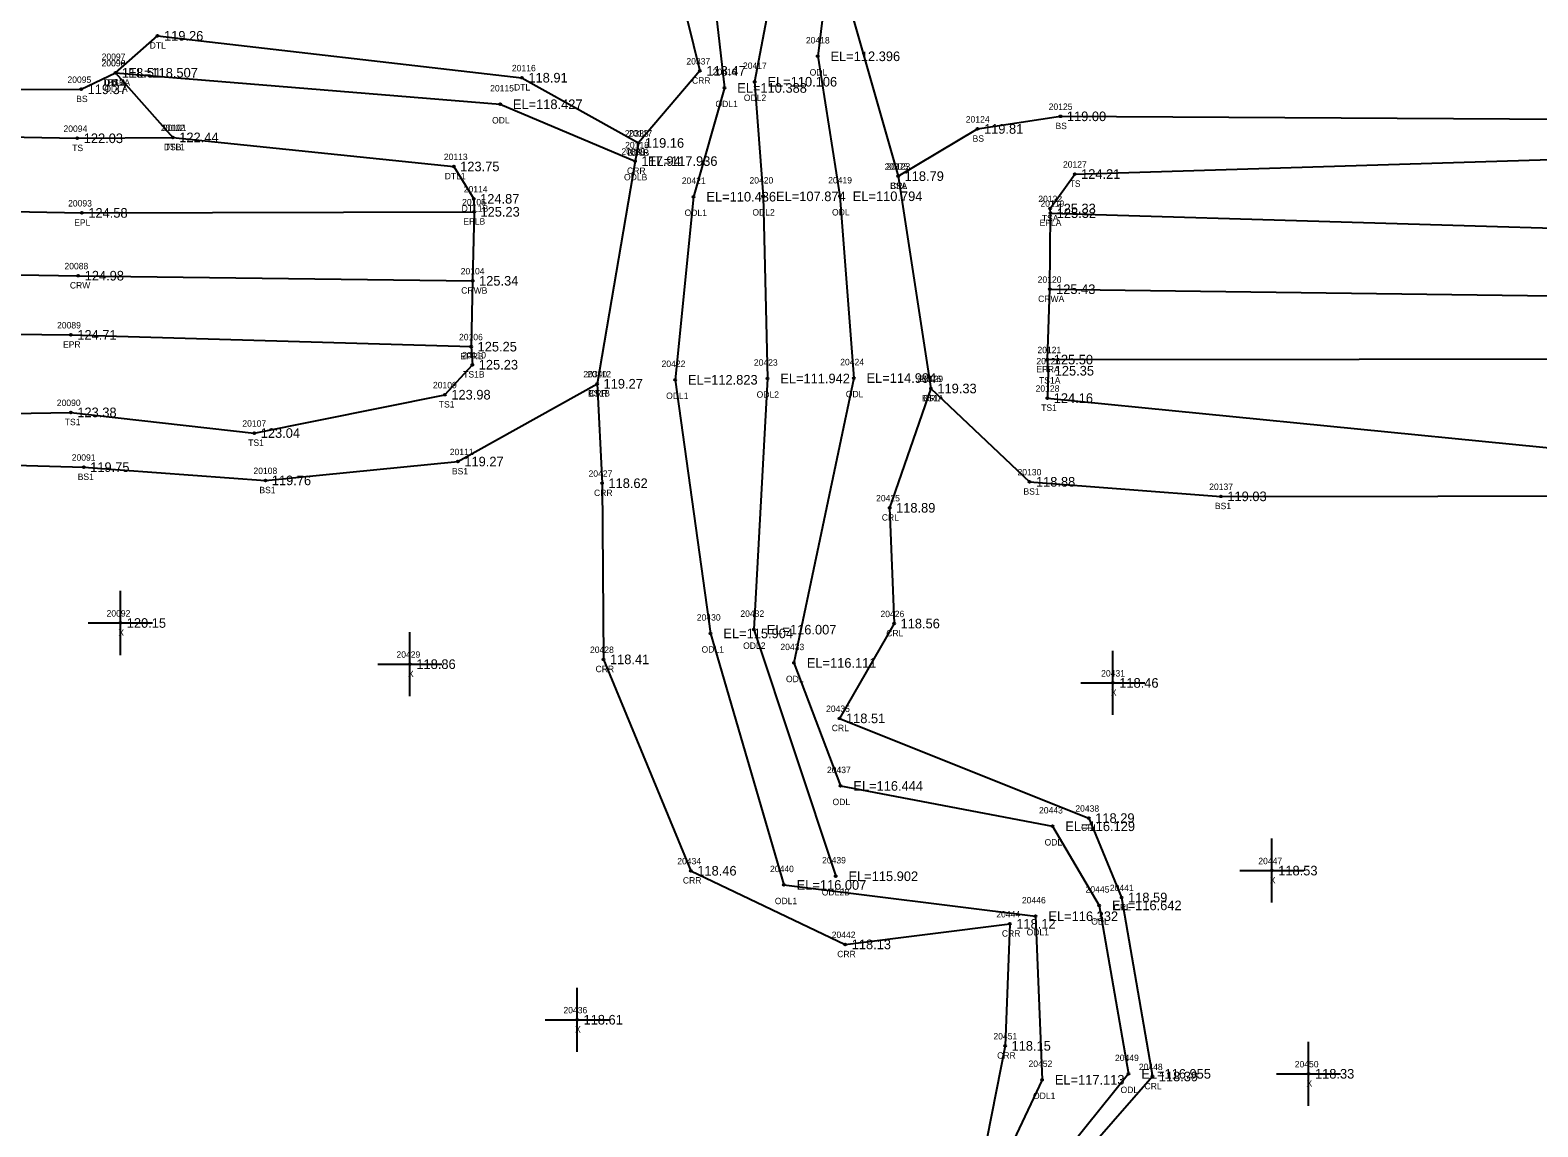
# Model space of a CAD drawing. Extents: x 2375812 to 2377225, y 1024470 to 1025135.
# Drawn here: x 2376402.6 to 2376638, y 1024795.6 to 1024966.8 of the extents above; entities that cross this region are included whole.
import ezdxf

# ---------------------------------------------------------------- set-up
doc = ezdxf.new("R2010")
doc.units = 0
for name, color, linetype in [('RD_DTM_BkLn1', 7, 'Continuous'), ('RD_DTM_BkLn2', 7, 'Continuous'), ('RD_DTM_BkLn_txCode', 7, 'Continuous'), ('RD_EX_H2O', 7, 'Continuous'), ('RD_EX_H2O_txCode', 7, 'Continuous'), ('RD_EX_Misc', 7, 'Continuous'), ('RD_EX_Misc_txCode', 7, 'Continuous'), ('RD_EX_Road', 7, 'Continuous'), ('RD_EX_Road_txCode', 7, 'Continuous'), ('RD_EX_TX_H2O_ELEV', 7, 'Continuous'), ('RD_EX_TX_Misc_ELEV', 7, 'Continuous'), ('RD_EX_TX_Road_ELEV', 7, 'Continuous'), ('RD_HC_Survey_ELEV', 7, 'Continuous'), ('RD_HC_Survey_txCode', 7, 'Continuous'), ('RD_SMD_Locator', 7, 'Continuous')]:
    doc.layers.add(name, color=color, linetype=linetype)

msp = doc.modelspace()

# ---------------------------------------------------------------- linework, layer by layer
at = {"layer": 'RD_DTM_BkLn1'}
for points in [[(2375816.52, 1024916.17), (2375868.08, 1024924.19), (2375918.61, 1024929.17), (2375973.79, 1024932.27), (2376030.31, 1024933.43), (2376124.39, 1024932.38), (2376221.5, 1024931.17), (2376315.07, 1024930.06), (2376410.07, 1024928.46), (2376471.65, 1024927.66)], [(2376561.75, 1024926.35), (2376659.86, 1024925.07), (2376762.41, 1024923.95), (2376865.76, 1024922.65), (2376965.3, 1024921.9), (2377063.64, 1024920.86), (2377113.34, 1024920.1), (2377166.94, 1024920.12), (2377217.3, 1024921.22)]]:
    msp.add_lwpolyline(points, dxfattribs=at)
at = {"layer": 'RD_DTM_BkLn2'}
for points in [[(2376029.54, 1024960.61), (2376031.93, 1024960.3), (2376124.75, 1024960.87), (2376220.58, 1024959.2), (2376313.51, 1024957.48), (2376410.53, 1024957.56), (2376415.87, 1024960.14)], [(2376030.33, 1024957.29), (2376124.82, 1024955.55), (2376220.6, 1024953.97), (2376313.35, 1024951.76), (2376409.92, 1024949.91), (2376424.84, 1024950.05)], [(2376538.09, 1024944), (2376550.49, 1024951.37), (2376563.43, 1024953.34), (2376659.84, 1024952.77), (2376765.68, 1024950.71), (2376864.8, 1024951), (2376966.18, 1024947.81), (2377065.88, 1024945.38), (2377115.79, 1024945.18), (2377168.04, 1024944.37), (2377216.91, 1024944.34)], [(2376561.81, 1024938.95), (2376565.65, 1024944.33), (2376658.56, 1024947.18), (2376764.14, 1024946.5), (2376864.38, 1024942.41), (2376965.82, 1024942.74), (2377065.85, 1024939.54), (2377114.14, 1024940.04), (2377167.94, 1024941.05), (2377217.02, 1024940.65)], [(2376471.81, 1024940.46), (2376471.87, 1024938.44), (2376471.65, 1024927.66), (2376471.42, 1024917.38), (2376471.6, 1024914.56)], [(2376561.53, 1024913.62), (2376561.38, 1024915.36), (2376561.75, 1024926.35), (2376561.85, 1024938.22), (2376561.81, 1024938.95)], [(2375828.21, 1024902.01), (2375869.58, 1024908.74), (2375919.97, 1024914.39), (2375974.42, 1024917.72), (2376030.13, 1024918.15), (2376124.55, 1024916.47), (2376157.47, 1024915.82), (2376169.1, 1024907.28), (2376220.97, 1024905.03), (2376312.67, 1024905.48), (2376408.92, 1024907.12), (2376437.56, 1024903.89), (2376467.32, 1024909.88), (2376471.6, 1024914.56)], [(2376561.53, 1024913.62), (2376561.38, 1024909.35), (2376658.21, 1024899.77), (2376672.96, 1024897.91), (2376688.03, 1024903.17), (2376760.99, 1024901.04), (2376828.16, 1024902.22), (2376853.81, 1024902.74), (2376860.1, 1024898.86), (2376865.34, 1024899.92), (2376875.73, 1024904.61), (2376896.78, 1024904.73), (2376899.24, 1024901.87), (2376965.55, 1024899.2), (2377063.48, 1024900.56), (2377114.6, 1024898.84), (2377167.13, 1024900.76), (2377217.62, 1024901.12)], [(2375828.74, 1024899.38), (2375869.85, 1024905.45), (2375920.89, 1024910.13), (2375974.62, 1024911.75), (2376029.89, 1024912.38), (2376123.86, 1024911.48), (2376128.27, 1024903.93), (2376220.97, 1024899.73), (2376312.35, 1024901.44), (2376410.93, 1024898.57), (2376439.29, 1024896.5), (2376469.35, 1024899.44), (2376491.09, 1024911.59)], [(2376543.21, 1024910.85), (2376558.6, 1024896.28), (2376588.49, 1024894.01), (2376656.25, 1024894.1), (2376679.22, 1024888.45), (2376688.36, 1024892.22), (2376760.25, 1024888.88), (2376862.95, 1024889.28), (2376867.73, 1024890.58), (2376879.38, 1024883.12), (2376893.75, 1024882.89), (2376900.24, 1024892.67), (2376965.04, 1024891.16), (2377064.46, 1024895.27), (2377115.01, 1024893.54), (2377167.33, 1024895.41), (2377217.32, 1024894.83)]]:
    msp.add_lwpolyline(points, dxfattribs=at)
at = {"layer": 'RD_EX_H2O'}
for points in [[(2376521.35, 1025122.45), (2376536.92, 1025091.14), (2376540.63, 1025083.08), (2376543.66, 1025055.12), (2376543.73, 1025030.97), (2376527.94, 1024982.48), (2376525.52, 1024962.71), (2376529, 1024940.86), (2376531.15, 1024912.48), (2376521.82, 1024868), (2376529.09, 1024848.8), (2376562.19, 1024842.5), (2376569.47, 1024830.15), (2376574.05, 1024803.85), (2376558.51, 1024784.52), (2376559.64, 1024766), (2376613.77, 1024719.65), (2376596.93, 1024694.68), (2376526.36, 1024664.12), (2376525.63, 1024655.55), (2376574.03, 1024595.3), (2376579.09, 1024545.56), (2376560.1, 1024512.81), (2376580.22, 1024476.29)], [(2376522.68, 1025124.28), (2376539.95, 1025091.93), (2376552.99, 1025053.79), (2376555.76, 1025047.24), (2376554.71, 1025040.88), (2376557.55, 1025026.68), (2376555.84, 1025015.85), (2376539.15, 1025001.14), (2376529.96, 1024972.45), (2376538.09, 1024944), (2376543.21, 1024910.85), (2376536.76, 1024892.22), (2376537.46, 1024874.15), (2376528.94, 1024859.35), (2376567.86, 1024843.78), (2376572.98, 1024831.38), (2376577.78, 1024803.44), (2376559.73, 1024782.76)], [(2376510.41, 1025118.87), (2376524.18, 1025090.35), (2376517.39, 1025079.83), (2376512.07, 1025056.47), (2376513.2, 1025032.16), (2376507.89, 1024984.65), (2376510.96, 1024957.77), (2376506.15, 1024940.79), (2376503.27, 1024912.21), (2376508.8, 1024872.61), (2376520.24, 1024833.34), (2376559.55, 1024828.46), (2376560.55, 1024802.93), (2376553.87, 1024788.72), (2376548.34, 1024764.64), (2376601.21, 1024719.97), (2376590.62, 1024704.71), (2376516.74, 1024677.65), (2376510.14, 1024650.4), (2376567.6, 1024571.64), (2376569.87, 1024553.24), (2376548.12, 1024513.5), (2376565.22, 1024475.98)], [(2376497.97, 1025114.18), (2376509.68, 1025107.56), (2376520.38, 1025090.17), (2376509.44, 1025080.09), (2376513.03, 1025070.01), (2376506.1, 1025057.18), (2376504.25, 1025038.92), (2376503.57, 1025008.7), (2376502.14, 1024980.74), (2376507.14, 1024960.43), (2376497.53, 1024949.18), (2376497, 1024946.35), (2376491.09, 1024911.59), (2376491.85, 1024896.06), (2376492.09, 1024868.56), (2376505.72, 1024835.56), (2376529.83, 1024824.06), (2376555.53, 1024827.27), (2376554.79, 1024808.22), (2376551.26, 1024790.28)], [(2376531.81, 1025089.31), (2376536.68, 1025082.46), (2376529.76, 1025051.44), (2376526.5, 1025031.27), (2376520.3, 1024983.09), (2376515.68, 1024958.74), (2376517.02, 1024940.85), (2376517.68, 1024912.41), (2376515.57, 1024873.2), (2376528.33, 1024834.7)], [(2376415.87, 1024960.14), (2376422.46, 1024965.91), (2376479.35, 1024959.37), (2376497.53, 1024949.18)], [(2376415.87, 1024960.14), (2376475.93, 1024955.22), (2376497, 1024946.35)], [(2376415.87, 1024960.14), (2376424.84, 1024950.05), (2376468.7, 1024945.51), (2376471.81, 1024940.46)]]:
    msp.add_lwpolyline(points, dxfattribs=at)
at = {"layer": 'RD_EX_Misc'}
for p, q in [((2376416.64, 1024869.24), (2376416.64, 1024879.24)), ((2376411.64, 1024874.24), (2376421.64, 1024874.24)), ((2376461.86, 1024862.81), (2376461.86, 1024872.81)), ((2376456.86, 1024867.81), (2376466.86, 1024867.81)), ((2376571.61, 1024859.88), (2376571.61, 1024869.88)), ((2376566.61, 1024864.88), (2376576.61, 1024864.88)), ((2376596.43, 1024830.58), (2376596.43, 1024840.58)), ((2376591.43, 1024835.58), (2376601.43, 1024835.58)), ((2376487.96, 1024807.3), (2376487.96, 1024817.3)), ((2376482.96, 1024812.3), (2376492.96, 1024812.3)), ((2376602.17, 1024798.86), (2376602.17, 1024808.86)), ((2376597.17, 1024803.86), (2376607.17, 1024803.86))]:
    msp.add_line(p, q, dxfattribs=at)
at = {"layer": 'RD_EX_Road'}
for points in [[(2375814.75, 1024926.04), (2375866.75, 1024934.16), (2375917.59, 1024939.49), (2375973.63, 1024942.9), (2376030.48, 1024943.85), (2376125.42, 1024942.84), (2376221.25, 1024941.27), (2376314.97, 1024940.08), (2376410.64, 1024938.26), (2376471.87, 1024938.44)], [(2376561.85, 1024938.22), (2376659.62, 1024935.3), (2376763.51, 1024933.89), (2376865.73, 1024932.88), (2376965.35, 1024932.49), (2377065.13, 1024930.78), (2377114.03, 1024930.18), (2377167.22, 1024930.19), (2377217.07, 1024931.12)], [(2375818.02, 1024906.46), (2375868.67, 1024914.36), (2375919.37, 1024919.49), (2375974.01, 1024923.01), (2376030.21, 1024923.67), (2376124.55, 1024922.83), (2376221.09, 1024921.25), (2376314, 1024920.33), (2376408.92, 1024919.22), (2376471.42, 1024917.38)], [(2376561.38, 1024915.36), (2376658.71, 1024915.48), (2376761.9, 1024913.76), (2376865.54, 1024912.46), (2376965.34, 1024911.98), (2377063.07, 1024911.1), (2377113.55, 1024910.69), (2377167.38, 1024909.96), (2377217.4, 1024910.82)]]:
    msp.add_lwpolyline(points, dxfattribs=at)
at = {"layer": 'RD_SMD_Locator'}
for centre in [(2376422.46, 1024965.91), (2376525.52, 1024962.71), (2376415.87, 1024960.14), (2376415.87, 1024960.14), (2376415.87, 1024960.14), (2376415.87, 1024960.14), (2376507.14, 1024960.43), (2376410.53, 1024957.56), (2376479.35, 1024959.37), (2376510.96, 1024957.77), (2376515.68, 1024958.74), (2376475.93, 1024955.22), (2376563.43, 1024953.34), (2376424.84, 1024950.05), (2376424.84, 1024950.05), (2376550.49, 1024951.37), (2376409.92, 1024949.91), (2376497.53, 1024949.18), (2376497.53, 1024949.18), (2376468.7, 1024945.51), (2376497, 1024946.35), (2376497, 1024946.35), (2376538.09, 1024944), (2376538.09, 1024944), (2376565.65, 1024944.33), (2376506.15, 1024940.79), (2376517.02, 1024940.85), (2376529, 1024940.86), (2376410.64, 1024938.26), (2376471.81, 1024940.46), (2376471.87, 1024938.44), (2376561.81, 1024938.95), (2376561.85, 1024938.22), (2376410.07, 1024928.46), (2376471.65, 1024927.66), (2376561.75, 1024926.35), (2376408.92, 1024919.22), (2376471.42, 1024917.38), (2376561.38, 1024915.36), (2376471.6, 1024914.56), (2376517.68, 1024912.41), (2376531.15, 1024912.48), (2376561.53, 1024913.62), (2376491.09, 1024911.59), (2376491.09, 1024911.59), (2376503.27, 1024912.21), (2376543.21, 1024910.85), (2376543.21, 1024910.85), (2376467.32, 1024909.88), (2376561.38, 1024909.35), (2376408.92, 1024907.12), (2376437.56, 1024903.89), (2376410.93, 1024898.57), (2376469.35, 1024899.44), (2376439.29, 1024896.5), (2376491.85, 1024896.06), (2376558.6, 1024896.28), (2376588.49, 1024894.01), (2376536.76, 1024892.22), (2376416.64, 1024874.24), (2376508.8, 1024872.61), (2376515.57, 1024873.2), (2376537.46, 1024874.15), (2376461.86, 1024867.81), (2376492.09, 1024868.56), (2376521.82, 1024868), (2376571.61, 1024864.88), (2376528.94, 1024859.35), (2376529.09, 1024848.8), (2376562.19, 1024842.5), (2376567.86, 1024843.78), (2376505.72, 1024835.56), (2376528.33, 1024834.7), (2376596.43, 1024835.58), (2376520.24, 1024833.34), (2376569.47, 1024830.15), (2376572.98, 1024831.38), (2376559.55, 1024828.46), (2376555.53, 1024827.27), (2376529.83, 1024824.06), (2376487.96, 1024812.3), (2376554.79, 1024808.22), (2376560.55, 1024802.93), (2376574.05, 1024803.85), (2376577.78, 1024803.44), (2376602.17, 1024803.86)]:
    msp.add_circle(centre, 0.15, dxfattribs=at)

# ---------------------------------------------------------------- texts
at = {"layer": 'RD_DTM_BkLn_txCode'}
for s, p in [('20096', (2376413.69, 1024961.14)), ('20095', (2376408.38, 1024958.56)), ('BSB', (2376414.62, 1024958.14)), ('BS', (2376409.75, 1024955.56)), ('20125', (2376561.59, 1024954.34)), ('20124', (2376548.65, 1024952.37)), ('20094', (2376407.76, 1024950.91)), ('20101', (2376423.25, 1024951.05)), ('BS', (2376549.71, 1024949.37)), ('BS', (2376562.65, 1024951.34)), ('TS', (2376409.12, 1024947.91)), ('TSB', (2376423.58, 1024948.05)), ('20123', (2376536.25, 1024945)), ('20127', (2376563.82, 1024945.33)), ('TS', (2376564.86, 1024942.33)), ('BSA', (2376536.82, 1024942)), ('20122', (2376559.97, 1024939.95)), ('TSA', (2376560.52, 1024936.95)), ('20110', (2376470.01, 1024915.56)), ('20126', (2376559.67, 1024914.62)), ('TS1B', (2376470.17, 1024912.56)), ('20112', (2376489.54, 1024912.59)), ('20129', (2376541.38, 1024911.85)), ('TS1A', (2376560.08, 1024911.62)), ('20109', (2376465.45, 1024910.88)), ('BS1B', (2376489.67, 1024909.59)), ('20128', (2376559.55, 1024910.35)), ('20090', (2376406.72, 1024908.12)), ('TS1', (2376466.36, 1024907.88)), ('BS1A', (2376541.78, 1024908.85)), ('TS1', (2376560.42, 1024907.35)), ('TS1', (2376407.96, 1024905.12)), ('20107', (2376435.69, 1024904.89)), ('TS1', (2376436.6, 1024901.89)), ('20111', (2376468.08, 1024900.44)), ('20091', (2376409.05, 1024899.57)), ('20108', (2376437.42, 1024897.5)), ('BS1', (2376468.41, 1024897.44)), ('BS1', (2376409.98, 1024896.57)), ('20130', (2376556.72, 1024897.28)), ('20137', (2376586.65, 1024895.01)), ('BS1', (2376438.35, 1024894.5)), ('BS1', (2376557.65, 1024894.28)), ('BS1', (2376587.54, 1024892.01))]:
    msp.add_text(s, height=1, dxfattribs=at).set_placement(p)
at = {"layer": 'RD_EX_H2O_txCode'}
for s, p in [('DTL', (2376421.22, 1024963.91)), ('20418', (2376523.68, 1024964.71)), ('20097', (2376413.72, 1024962.14)), ('20098', (2376413.72, 1024961.14)), ('20099', (2376413.72, 1024961.14)), ('20337', (2376505.02, 1024961.43)), ('20116', (2376477.78, 1024960.37)), ('20416', (2376509.11, 1024959.77)), ('20417', (2376513.85, 1024960.74)), ('ODL', (2376524.27, 1024959.71)), ('DTL1A', (2376413.98, 1024958.14)), ('ODLA', (2376414.14, 1024957.14)), ('DTLA', (2376414.14, 1024958.14)), ('20115', (2376474.38, 1024957.22)), ('DTL', (2376478.11, 1024957.37)), ('CRR', (2376505.89, 1024958.43)), ('ODL1', (2376509.56, 1024954.77)), ('ODL2', (2376513.99, 1024955.74)), ('ODL', (2376474.68, 1024952.22)), ('20102', (2376422.97, 1024951.05)), ('20338', (2376495.41, 1024950.18)), ('20117', (2376495.97, 1024950.18)), ('DTL1', (2376423.43, 1024948.05)), ('20339', (2376494.88, 1024947.35)), ('20118', (2376495.45, 1024948.35)), ('DTLB', (2376495.81, 1024947.18)), ('CRR', (2376496.27, 1024947.18)), ('20113', (2376467.15, 1024946.51)), ('20375', (2376535.97, 1024945)), ('DTL1', (2376467.29, 1024943.51)), ('ODLB', (2376495.28, 1024943.35)), ('CRR', (2376495.75, 1024944.35)), ('20421', (2376504.31, 1024942.79)), ('20420', (2376514.87, 1024942.85)), ('20419', (2376527.16, 1024942.86)), ('20114', (2376470.26, 1024941.46)), ('CRL', (2376536.86, 1024942)), ('DTL1B', (2376469.93, 1024938.46)), ('ODL1', (2376504.74, 1024937.79)), ('ODL2', (2376515.33, 1024937.85)), ('ODL', (2376527.76, 1024937.86)), ('20422', (2376501.15, 1024914.21)), ('20423', (2376515.56, 1024914.41)), ('20424', (2376529.04, 1024914.48)), ('20340', (2376488.93, 1024912.59)), ('20376', (2376541.07, 1024911.85)), ('CRR', (2376489.83, 1024909.59)), ('ODL1', (2376501.86, 1024909.21)), ('ODL2', (2376515.99, 1024909.41)), ('ODL', (2376529.91, 1024909.48)), ('CRL', (2376541.99, 1024908.85)), ('20427', (2376489.74, 1024897.06)), ('CRR', (2376490.6, 1024894.06)), ('20425', (2376534.64, 1024893.22)), ('CRL', (2376535.53, 1024890.22)), ('20430', (2376506.65, 1024874.61)), ('20432', (2376513.45, 1024875.2)), ('20426', (2376535.32, 1024875.15)), ('CRL', (2376536.23, 1024872.15)), ('20428', (2376489.97, 1024869.56)), ('ODL1', (2376507.39, 1024869.61)), ('ODL2', (2376513.88, 1024870.2)), ('20433', (2376519.7, 1024870)), ('CRR', (2376490.84, 1024866.56)), ('ODL', (2376520.57, 1024865)), ('20435', (2376526.83, 1024860.35)), ('CRL', (2376527.72, 1024857.35)), ('20437', (2376526.97, 1024850.8)), ('ODL', (2376527.84, 1024845.8)), ('20443', (2376560.08, 1024844.5)), ('20438', (2376565.75, 1024844.78)), ('CRL', (2376566.64, 1024841.78)), ('ODL', (2376560.95, 1024839.5)), ('20434', (2376503.6, 1024836.56)), ('20439', (2376526.21, 1024836.7)), ('20440', (2376518.08, 1024835.34)), ('CRR', (2376504.47, 1024833.56)), ('ODL2B', (2376526.16, 1024831.7)), ('20445', (2376567.35, 1024832.15)), ('20441', (2376571.14, 1024832.38)), ('ODL1', (2376518.83, 1024830.34)), ('20446', (2376557.41, 1024830.46)), ('CRL', (2376571.75, 1024829.38)), ('20444', (2376553.41, 1024828.27)), ('ODL', (2376568.23, 1024827.15)), ('20442', (2376527.71, 1024825.06)), ('CRR', (2376554.28, 1024825.27)), ('ODL1', (2376558.14, 1024825.46)), ('CRR', (2376528.57, 1024822.06)), ('20451', (2376552.96, 1024809.22)), ('CRR', (2376553.54, 1024806.22)), ('20449', (2376571.94, 1024805.85)), ('20452', (2376558.44, 1024804.93)), ('20448', (2376575.67, 1024804.44)), ('ODL', (2376572.81, 1024800.85)), ('CRL', (2376576.55, 1024801.44)), ('ODL1', (2376559.14, 1024799.93))]:
    msp.add_text(s, height=1, dxfattribs=at).set_placement(p)
at = {"layer": 'RD_EX_Misc_txCode'}
for s, p in [('20092', (2376414.49, 1024875.24)), ('X', (2376416.33, 1024872.24)), ('20429', (2376459.75, 1024868.81)), ('X', (2376461.55, 1024865.81)), ('20431', (2376569.78, 1024865.88)), ('X', (2376571.3, 1024862.88)), ('20447', (2376594.32, 1024836.58)), ('X', (2376596.12, 1024833.58)), ('20436', (2376485.82, 1024813.3)), ('X', (2376487.64, 1024810.3)), ('20450', (2376600.01, 1024804.86)), ('X', (2376601.85, 1024801.86))]:
    msp.add_text(s, height=1, dxfattribs=at).set_placement(p)
at = {"layer": 'RD_EX_Road_txCode'}
for s, p in [('20093', (2376408.48, 1024939.26)), ('20105', (2376470, 1024939.44)), ('20119', (2376560.3, 1024939.22)), ('EPL', (2376409.43, 1024936.26)), ('EPLB', (2376470.19, 1024936.44)), ('EPLA', (2376560.16, 1024936.22)), ('20089', (2376406.76, 1024920.22)), ('EPR', (2376407.69, 1024917.22)), ('20106', (2376469.52, 1024918.38)), ('20121', (2376559.83, 1024916.36)), ('EPRB', (2376469.72, 1024915.38)), ('EPRA', (2376559.66, 1024913.36))]:
    msp.add_text(s, height=1, dxfattribs=at).set_placement(p)
at = {"layer": 'RD_EX_TX_H2O_ELEV'}
for s, p in [('119.26', (2376423.46, 1024965.16)), ('EL=112.396', (2376527.52, 1024961.96)), ('118.51', (2376416.87, 1024959.39)), ('118.51', (2376416.87, 1024959.39)), ('EL=118.507', (2376417.87, 1024959.39)), ('118.91', (2376480.35, 1024958.62)), ('118.47', (2376508.14, 1024959.68)), ('EL=110.388', (2376512.96, 1024957.02)), ('EL=110.106', (2376517.68, 1024957.99)), ('EL=118.427', (2376477.93, 1024954.47)), ('122.44', (2376425.84, 1024949.3)), ('119.16', (2376498.53, 1024948.43)), ('119.16', (2376498.53, 1024948.43)), ('123.75', (2376469.7, 1024944.76)), ('117.94', (2376498, 1024945.6)), ('EL=117.936', (2376499, 1024945.6)), ('118.79', (2376539.09, 1024943.25)), ('124.87', (2376472.81, 1024939.71)), ('EL=110.436', (2376508.15, 1024940.04)), ('EL=107.874', (2376519.02, 1024940.1)), ('EL=110.794', (2376531, 1024940.11)), ('EL=112.823', (2376505.27, 1024911.46)), ('EL=111.942', (2376519.68, 1024911.66)), ('EL=114.994', (2376533.15, 1024911.73)), ('119.27', (2376492.09, 1024910.84)), ('119.33', (2376544.21, 1024910.1)), ('118.62', (2376492.85, 1024895.31)), ('118.89', (2376537.76, 1024891.47)), ('118.56', (2376538.46, 1024873.4)), ('EL=115.904', (2376510.8, 1024871.86)), ('EL=116.007', (2376517.57, 1024872.45)), ('118.41', (2376493.09, 1024867.81)), ('EL=116.111', (2376523.82, 1024867.25)), ('118.51', (2376529.94, 1024858.6)), ('EL=116.444', (2376531.09, 1024848.05)), ('118.29', (2376568.86, 1024843.03)), ('EL=116.129', (2376564.19, 1024841.75)), ('118.46', (2376506.72, 1024834.81)), ('EL=115.902', (2376530.33, 1024833.95)), ('EL=116.007', (2376522.24, 1024832.59)), ('EL=116.642', (2376571.47, 1024829.4)), ('118.59', (2376573.98, 1024830.63)), ('118.12', (2376556.53, 1024826.52)), ('EL=116.332', (2376561.55, 1024827.71)), ('118.13', (2376530.83, 1024823.31)), ('118.15', (2376555.79, 1024807.47)), ('EL=116.955', (2376576.05, 1024803.1)), ('118.39', (2376578.78, 1024802.69)), ('EL=117.113', (2376562.55, 1024802.18))]:
    msp.add_text(s, height=1.5, dxfattribs=at).set_placement(p)
at = {"layer": 'RD_EX_TX_Misc_ELEV'}
for s, p in [('118.51', (2376416.87, 1024959.39)), ('119.37', (2376411.53, 1024956.81)), ('119.00', (2376564.43, 1024952.59)), ('122.03', (2376410.92, 1024949.16)), ('122.44', (2376425.84, 1024949.3)), ('119.81', (2376551.49, 1024950.62)), ('118.79', (2376539.09, 1024943.25)), ('124.21', (2376566.65, 1024943.58)), ('125.33', (2376562.81, 1024938.2)), ('125.23', (2376472.6, 1024913.81)), ('125.35', (2376562.53, 1024912.87)), ('123.98', (2376468.32, 1024909.13)), ('119.27', (2376492.09, 1024910.84)), ('119.33', (2376544.21, 1024910.1)), ('124.16', (2376562.38, 1024908.6)), ('123.38', (2376409.92, 1024906.37)), ('123.04', (2376438.56, 1024903.14)), ('119.75', (2376411.93, 1024897.82)), ('119.27', (2376470.35, 1024898.69)), ('119.76', (2376440.29, 1024895.75)), ('118.88', (2376559.6, 1024895.53)), ('119.03', (2376589.49, 1024893.26)), ('120.15', (2376417.64, 1024873.49)), ('118.86', (2376462.86, 1024867.06)), ('118.46', (2376572.61, 1024864.13)), ('118.53', (2376597.43, 1024834.83)), ('118.61', (2376488.96, 1024811.55)), ('118.33', (2376603.17, 1024803.11))]:
    msp.add_text(s, height=1.5, dxfattribs=at).set_placement(p)
at = {"layer": 'RD_EX_TX_Road_ELEV'}
for s, p in [('124.58', (2376411.64, 1024937.51)), ('125.23', (2376472.87, 1024937.69)), ('125.32', (2376562.85, 1024937.47)), ('124.71', (2376409.92, 1024918.47)), ('125.25', (2376472.42, 1024916.63)), ('125.50', (2376562.38, 1024914.61))]:
    msp.add_text(s, height=1.5, dxfattribs=at).set_placement(p)
at = {"layer": 'RD_HC_Survey_ELEV'}
for s, p in [('124.98', (2376411.07, 1024927.71)), ('125.34', (2376472.65, 1024926.91)), ('125.43', (2376562.75, 1024925.6))]:
    msp.add_text(s, height=1.5, dxfattribs=at).set_placement(p)
at = {"layer": 'RD_HC_Survey_txCode'}
for s, p in [('20088', (2376407.91, 1024929.46)), ('20104', (2376469.78, 1024928.66)), ('CRW', (2376408.76, 1024926.46)), ('CRWB', (2376469.86, 1024925.66)), ('20120', (2376559.87, 1024927.35)), ('CRWA', (2376559.94, 1024924.35))]:
    msp.add_text(s, height=1, dxfattribs=at).set_placement(p)

doc.saveas('drawing.dxf')
